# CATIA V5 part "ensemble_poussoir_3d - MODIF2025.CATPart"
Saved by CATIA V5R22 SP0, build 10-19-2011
Part number: Poussoir_flacon
Bounding box of the stored display mesh (mm): x 82 to 187, y 0 to 48, z 0 to 46
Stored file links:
  D:\PER\CAO_PER_MODIF_2025\CAO_PER_pick&place_2024P\Sous_Ensemble_Flacon\ensemble_poussoir_3d - MODIF2025.CATPart
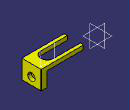
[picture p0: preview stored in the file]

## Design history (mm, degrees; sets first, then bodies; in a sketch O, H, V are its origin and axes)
Set1
  Plane1: type Offset, RefPlane face of Pocket3 from Sketch4.L1, Offset 16, reversed
Body1 (main body)
  Sketch1 on yz-plane, origin (0, 0, 0), H (0, 1, 0), V (0, 0, 1)
    line L1 (0, 0) -> (48, 0)
    line L2 (48, 0) -> (48, 46)
    line L3 (48, 46) -> (0, 46)
    line L4 (0, 46) -> (0, 0)
    point P1 (48, 0)
    point P2 (48, 46)
    point P3 (0, 46)
    distance P1 P2 = 46
    distance P2 P3 = 48
    horizontal: L1 H, L3 H
    vertical: L2 V, L4 V
  Pad1: profile Sketch1, direction (1, 0, 0), length 187
  Sketch2 on face of Pad1 from Sketch1.L4, origin (0, 0, 0), H (1, 0, 0), V (0, 0, 1)
    point P1 (15, 0)
    line L1 (15, 0) -> (173, 0)
    line L2 (173, 0) -> (173, 36)
    line L3 (173, 36) -> (15, 36)
    line L4 (15, 36) -> (15, 0)
    reference projected line E1 (0, 46) -> (187, 46) from edge [face of Pad1 from Sketch1.L4 | face of Pad1 from Sketch1.L3]
    reference projected line E2 (187, 46) -> (187, 0) from edge [face of Pad1 from Sketch1.L4 | end face of Pad1]
    reference projected line E3 (0, 46) -> (0, 0) from edge [start face of Pad1 | face of Pad1 from Sketch1.L4]
    distance L3 E1 = 10
    distance L2 E2 = 14
    distance L4 E3 = 15
    coincidence: P1 H
    horizontal: L1 H, L3 H
    vertical: L2 V, L4 V
  Pocket1: profile Sketch2, direction (0, 1, 0), through (limit type 3)
  Sketch3 on start face of Pad1, origin (0, 0, 0), H (0, -1, 0), V (0, 0, 1)
    line L1 (-41, 0) -> (-7, 0)
    line L2 (-7, 0) -> (-7, 31.5)
    line L3 (-41, 31.5) -> (-41, 0)
    point P2 (-7, 0)
    point P3 (-7, 49)
    point P4 (-41, 49)
    reference projected line E1 (0, 46) -> (0, 0) from edge [start face of Pad1 | face of Pad1 from Sketch1.L4]
    reference projected line E2 (-48, 0) -> (-48, 46) from edge [start face of Pad1 | face of Pad1 from Sketch1.L2]
    reference projected line E3 (0, 0) -> (-48, 0) from edge [start face of Pad1 | face of Pad1 from Sketch1.L1]
    point P5 (-7, 31.5)
    point P6 (-41, 31.5)
    arc A1 centre (-24, 25.5839) radius 18 from (-7, 31.5) to (-41, 31.5) ccw
    point P8 (-7, 31.5)
    point P9 (-41, 31.5)
    distance L2 E1 = 7
    distance L3 E2 = 7
    length L3 = 31.5
    radius A1 = 18
    distance P5 P2 = 31.5
    horizontal: L1 H
    vertical: L2 V, L3 V
    coincidence: E3 L1, L3 P6, L2 P5, P5 P8, P6 P9
  Pocket2: profile Sketch3, direction (1, 0, 0), up to face of Pocket1 from Sketch2.L4
  Sketch4 on face of Pad1 from Sketch1.L3, origin (0, 0, 46), H (1, 0, 0), V (0, 1, 0)
    point P1 (90, 24)
    line L1 (148, 8) -> (28, 8)
    line L2 (28, 40) -> (148, 40)
    point P3 (148, 8)
    point P4 (28, 8)
    arc A1 centre (148, 24) radius 16 from (148, 40) to (148, 8) cw
    arc A2 centre (28, 24) radius 16 from (28, 8) to (28, 40) cw
    point P7 (28, 24)
    reference projected line E1 (0, 48) -> (0, 0) from edge [start face of Pad1 | face of Pad1 from Sketch1.L3]
    distance L1 L2 = 32
    distance P3 P4 = 120
    radius A1 = 16
    radius A2 = 16
    distance P7 E1 = 28
    horizontal: L1 H, L2 H
    equidistance: L1 L2 P1
    fix: P1
  Pocket3: profile Sketch4, direction (0, 0, -1), through (limit type 3)
  Sketch5 on face of Pocket1 from Sketch2.L2, origin (173, 0, 0), H (0, 1, 0), V (0, 0, 1)
    circle A1 centre (24, 18) radius 4.25
    point P1 (24, 18)
    reference projected line E1 (48, 0) -> (48, 46) from edge [face of Pad1 from Sketch1.L2 | end face of Pad1]
    reference projected line E2 (0, 0) -> (48, 0) from edge [face of Pad1 from Sketch1.L1 | end face of Pad1]
    distance P1 E1 = 24
    radius A1 = 4.25
    distance P1 E2 = 18
  Pocket4: profile Sketch5, direction (1, 0, 0), length 7.5, opposite side through (limit type 3)
  Sketch6 on end face of Pad1, origin (187, 0, 0), H (0, 1, 0), V (0, 0, 1)
    circle A1 centre (24, 18) radius 9
    reference projected circle E1 centre (24, 18) radius 4.25 from Sketch5.A1
    radius A1 = 9
    concentricity: E1 A1
  Pocket5: profile Sketch6, direction (-1, 0, 0), length 9
  Sketch7 on face of Pad1 from Sketch1.L3, origin (0, 0, 46), H (1, 0, 0), V (0, 1, 0)
    point P2 (82, 0)
    line L1 (82, 48) -> (0, 48)
    point P3 (0, 48)
    point P4 (0, 48)
    line L2 (0, 48) -> (0, 0)
    point P5 (0, 0)
    line L3 (0, 0) -> (82, 0)
    reference projected line E1 (0, 48) -> (187, 48) from edge [face of Pad1 from Sketch1.L3 | face of Pad1 from Sketch1.L2]
    reference projected line E2 (0, 48) -> (0, 0) from edge [start face of Pad1 | face of Pad1 from Sketch1.L3]
    line L4 (82, 48) -> (82, 0)
    point P6 (82, 0)
    reference projected line E3 (187, 48) -> (187, 0) from edge [face of Pad1 from Sketch1.L3 | end face of Pad1]
    distance E3 L4 = 105
    horizontal: L1 H, L3 H
    coincidence: P5 H, E1 P4, P3 P4, L2 E2, P6 L3, P6 P2
    vertical: L2 V, L4 V
  Pocket6: profile Sketch7, direction (0, 0, -1), length 187
  Chamfer1: length 1, angle 45, on edge [face of Pad1 from Sketch1.L2 | end face of Pad1]
  Chamfer2: length 1, angle 45, on edge [face of Pad1 from Sketch1.L4 | end face of Pad1]
  Chamfer3: length 1, angle 45, on edge [face of Pocket6 from Sketch7.L4 | face of Pad1 from Sketch1.L4]
  Chamfer4: length 1, angle 45, on edge [face of Pad1 from Sketch1.L2 | face of Pocket6 from Sketch7.L4]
